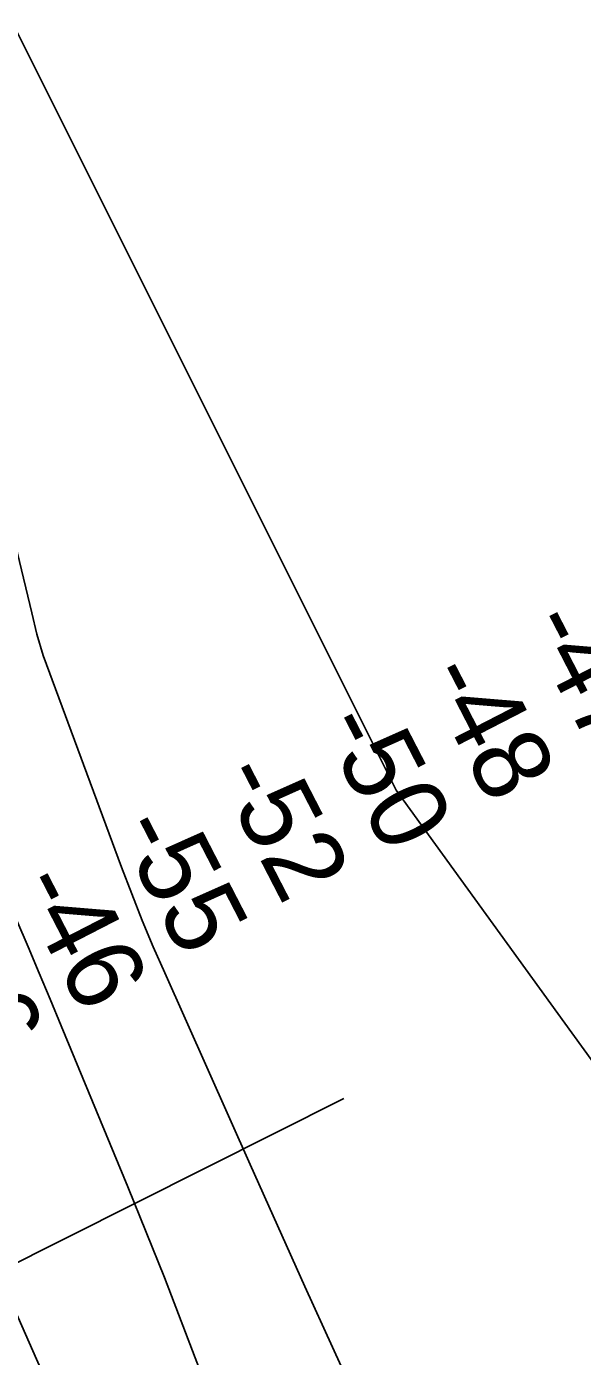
# Model space of a CAD drawing. Extents: x 3684037 to 3722149, y 433263 to 459021.
# Drawn here: x 3708721 to 3709206, y 440941 to 442103 of the extents above; entities that cross this region are included whole.
import ezdxf

# ---------------------------------------------------------------- set-up
doc = ezdxf.new("R2010")
doc.units = 0
for name, color, linetype in [('V-RIVR-EDGE', 7, 'Continuous'), ('V-RIVR-RANG', 7, 'Continuous'), ('V-TOPO-DPTH', 7, 'Continuous'), ('V-TOPO-MAJR', 7, 'Continuous'), ('V-TOPO-MINR', 7, 'Continuous')]:
    doc.layers.add(name, color=color, linetype=linetype)

msp = doc.modelspace()

# ---------------------------------------------------------------- linework, layer by layer
at = {"layer": 'V-RIVR-EDGE'}
msp.add_spline([(3705459.2609885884, 448025.4338505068), (3705478.181262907, 447991.0156329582), (3705490.6466582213, 447962.67892349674), (3705497.886274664, 447946.89059973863), (3705515.196078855, 447915.30695303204), (3705550.2240541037, 447853.7561290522), (3705577.199678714, 447806.37815928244), (3705592.0892782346, 447777.22671585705), (3705613.0133912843, 447735.5248869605), (3705627.0852571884, 447702.7361373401), (3705648.4127376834, 447660.6289412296), (3705670.9403216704, 447613.2619701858), (3705688.6394949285, 447575.6118136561), (3705703.1157281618, 447542.82206415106), (3705728.0505183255, 447487.76611454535), (3705750.155737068, 447433.12153145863), (3705764.2256032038, 447399.5240471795), (3705787.557922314, 447350.5376070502), (3705800.426685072, 447321.79553037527), (3705823.7710027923, 447277.66149819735), (3705853.129836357, 447212.8897339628), (3705867.200702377, 447179.69661701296), (3705884.5115064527, 447148.517337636), (3705906.216357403, 447095.49122375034), (3705936.00155575, 447039.61454087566), (3705952.47362864, 446996.3062413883), (3705954.4714680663, 446986.5964260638), (3705964.512659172, 446959.0744505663), (3705978.185157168, 446928.3085374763), (3706001.9328423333, 446883.76913808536), (3706017.2158104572, 446850.1686541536), (3706031.3046743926, 446824.25414913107), (3706060.2971362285, 446774.8493432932), (3706084.8695541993, 446736.77782140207), (3706095.754475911, 446723.40670266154), (3706096.150844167, 446720.17076414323), (3706091.2844378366, 446714.52162014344), (3706089.663968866, 446713.31251769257), (3706090.461704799, 446708.86247730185), (3706096.1148483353, 446705.61354028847), (3706102.9840935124, 446703.5747056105), (3706108.6282380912, 446696.68646263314), (3706116.2782211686, 446683.3233429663), (3706129.961717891, 446657.0054704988), (3706163.363224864, 446591.8193400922), (3706169.3887394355, 446575.6296486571), (3706187.0869128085, 446537.5751247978), (3706212.808440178, 446473.6210941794), (3706230.094247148, 446432.33263156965), (3706247.398052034, 446398.3227808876), (3706265.123222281, 446371.18617491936), (3706278.8077188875, 446345.27266978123), (3706293.681320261, 446309.65134908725), (3706314.591434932, 446262.28837758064), (3706333.5067098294, 446225.8483233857), (3706356.038293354, 446180.09882165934), (3706380.1853464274, 446133.5365857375), (3706396.283048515, 446102.36030601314), (3706412.7941168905, 446074.82233236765), (3706429.688555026, 446038.79164492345), (3706446.9753618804, 445997.9075496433), (3706455.379085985, 445962.3022270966), (3706478.2400455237, 445886.2241757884), (3706492.7132791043, 445852.221324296), (3706510.4004537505, 445809.7187598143), (3706528.098627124, 445771.6642359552), (3706558.2621958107, 445705.27300263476), (3706582.809616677, 445657.09229751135), (3706597.6902172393, 445624.3015481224), (3706628.25915314, 445558.3136822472), (3706659.6138263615, 445483.02336802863), (3706677.6863705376, 445432.8368244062), (3706696.968017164, 445381.0298118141), (3706750.0515385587, 445262.4181996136), (3706782.6343120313, 445193.1903956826), (3706806.7693664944, 445141.77575180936), (3706827.6774813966, 445093.60404564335), (3706850.971804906, 445029.251647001), (3706864.204939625, 444984.33387727), (3706871.8019288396, 444949.5392891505), (3706889.464106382, 444896.92754143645), (3706899.900665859, 444865.76526009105), (3706912.3530626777, 444832.1717753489), (3706928.848132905, 444798.1639244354), (3706942.5356291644, 444773.46352128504), (3706966.274315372, 444725.28481592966), (3706990.4233682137, 444679.53131466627), (3707016.9756276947, 444624.4713655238), (3707033.864066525, 444586.0144741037), (3707080.5137064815, 444481.9760839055), (3707095.3833083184, 444444.7372938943), (3707112.268747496, 444405.0673004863), (3707123.1276722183, 444381.1826311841), (3707171.385782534, 444273.5009354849), (3707203.15082239, 444200.6358253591), (3707218.0214241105, 444163.8014026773), (3707250.203829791, 444096.19206794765), (3707257.428447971, 444074.33823424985), (3707269.882844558, 444041.55348416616), (3707288.3577562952, 443990.55720600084), (3707304.028093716, 443950.0814775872), (3707342.974756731, 443837.9747386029), (3707365.860713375, 443772.0058705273), (3707378.693480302, 443728.70656999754), (3707379.8705864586, 443714.14634649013), (3707381.055691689, 443702.8210616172), (3707387.4745748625, 443682.1823296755), (3707398.330499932, 443657.0845583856), (3707418.0505099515, 443619.02503510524), (3707438.977622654, 443578.5363081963), (3707454.253591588, 443542.10525295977), (3707473.1368701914, 443492.7254442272), (3707483.176061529, 443464.3947340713), (3707531.0578012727, 443368.0363234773), (3707542.7274604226, 443344.9583890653), (3707550.7628130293, 443323.91129025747), (3707556.775329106, 443302.4648235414), (3707556.7633304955, 443297.61241559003), (3707558.764169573, 443289.1157022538), (3707568.429989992, 443273.3213791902), (3707583.724956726, 443244.5733032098), (3707593.778146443, 443221.9037356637), (3707598.205189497, 443213.40102302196), (3707609.506477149, 443204.8813123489), (3707611.9086839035, 443195.17049714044), (3707611.872688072, 443180.6132732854), (3707615.480997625, 443168.06888711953), (3707621.9068799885, 443150.26072648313), (3707634.3842739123, 443126.77642497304), (3707648.071770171, 443102.0760218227), (3707655.300387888, 443081.8396574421), (3707660.5361656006, 443073.3349450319), (3707674.23066105, 443051.46511318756), (3707678.635706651, 443034.0663193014), (3707682.6333852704, 443015.4554233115), (3707689.4656347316, 442998.4549974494), (3707701.917031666, 442964.4571453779), (3707713.9590618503, 442928.4384565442), (3707721.175680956, 442903.349684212), (3707726.3964604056, 442888.7794618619), (3707738.081117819, 442871.7670373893), (3707743.706264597, 442857.1958151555), (3707744.4850027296, 442845.0627955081), (3707747.2685794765, 442826.050531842), (3707753.7124597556, 442815.5209831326), (3707762.977912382, 442801.34512927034), (3707770.2135292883, 442783.9393361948), (3707772.585739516, 442762.0975011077), (3707776.166052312, 442738.23082972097), (3707779.760363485, 442720.02530094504), (3707786.591613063, 442702.6205077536), (3707805.499888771, 442663.34988225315), (3707822.7986942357, 442627.3181949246), (3707832.0301507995, 442599.39385186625), (3707839.2457700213, 442573.9007122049), (3707845.6846508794, 442561.3493268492), (3707852.5368980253, 442552.4362475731), (3707860.193880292, 442541.9036992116), (3707869.4663321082, 442530.55841665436), (3707886.3937664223, 442507.8718510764), (3707898.8601616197, 442479.9395089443), (3707916.135969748, 442434.60737304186), (3707928.5753680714, 442395.7571130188), (3707943.439970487, 442356.49648636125), (3707965.5811850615, 442316.40912712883), (3707989.726238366, 442269.0381565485), (3708009.8426166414, 442227.7426947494), (3708024.7172178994, 442192.5257413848), (3708061.3216672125, 442114.39185736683), (3708074.19742916, 442088.4803519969), (3708094.3098078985, 442045.5674208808), (3708116.024657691, 441996.5849802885), (3708126.0638490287, 441968.25427013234), (3708137.690513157, 441927.7885405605), (3708147.3253371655, 441899.4588302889), (3708157.761896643, 441868.2965489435), (3708179.0553810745, 441812.4408636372), (3708203.964174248, 441746.87136346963), (3708227.690861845, 441693.8402501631), (3708249.813078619, 441646.06991167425), (3708265.103045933, 441615.29999904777), (3708271.524928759, 441595.87436909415), (3708278.365177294, 441582.10888186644), (3708308.1063807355, 441508.4400365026), (3708330.6259656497, 441457.8381268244), (3708349.905612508, 441405.22237957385), (3708369.558630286, 441340.0702452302), (3708384.005866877, 441295.5538431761), (3708395.2611598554, 441268.4332353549), (3708411.757229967, 441234.82975177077), (3708423.4208898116, 441209.32561338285), (3708441.1150636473, 441169.65362020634), (3708458.4178686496, 441135.239402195), (3708469.274793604, 441110.54599823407), (3708475.28730968, 441089.09953151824), (3708486.945970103, 441061.5735564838), (3708507.055349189, 441017.44752338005), (3708523.5384208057, 440978.58726451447), (3708539.202758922, 440935.68533212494), (3708564.1435483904, 440883.0555864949), (3708587.089498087, 440841.3487581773), (3708595.1408488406, 440826.77153663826), (3708600.3546291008, 440809.3707429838), (3708606.7475152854, 440778.2184604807), (3708615.5866031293, 440755.14752525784), (3708636.8620896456, 440692.013228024), (3708652.91879648, 440644.25788779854), (3708673.412545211, 440592.04350822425), (3708688.685514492, 440554.3993509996), (3708705.9553233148, 440506.6410111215), (3708725.6613349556, 440462.92034523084), (3708743.353509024, 440422.43961739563), (3708759.4422121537, 440387.62403170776), (3708800.050339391, 440293.3054556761), (3708820.961453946, 440246.3468514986), (3708835.028320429, 440211.5362652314), (3708849.1041858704, 440180.3649849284), (3708876.059812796, 440124.89966857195), (3708892.157514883, 440093.72338884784), (3708912.2798924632, 440054.8541310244), (3708922.3300825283, 440030.97146149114), (3708931.9579073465, 439999.8111799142), (3708939.1845252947, 439978.7660808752), (3708948.0196136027, 439954.0776763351), (3708952.412660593, 439931.82647449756), (3708956.0019723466, 439911.59910907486), (3708960.015649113, 439899.45809035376), (3708969.6484733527, 439870.3196454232), (3708986.9362800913, 439829.8399174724), (3708999.3836774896, 439794.22459608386), (3709014.653647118, 439755.36733687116), (3709034.7480279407, 439705.1757938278), (3709046.79605743, 439671.58330896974), (3709063.280128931, 439633.1274174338), (3709075.7695214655, 439614.49552387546), (3709093.103322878, 439592.6166930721), (3709105.998082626, 439574.38816695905), (3709121.705415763, 439548.8740297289), (3709151.4686166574, 439484.1012656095), (3709171.5959936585, 439447.2538444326), (3709197.377514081, 439407.5618535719), (3709211.0500120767, 439376.7959404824), (3709222.3063049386, 439350.0796999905), (3709240.400846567, 439308.789237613), (3709252.8692415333, 439281.6656301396), (3709266.1473710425, 439254.94439022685), (3709270.9767816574, 439245.6319430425), (3709296.338936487, 439199.87544212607), (3709313.2213760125, 439158.99234673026), (3709331.3089184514, 439114.8713130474), (3709341.338110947, 439082.49692959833), (3709360.25438573, 439046.46124273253), (3709378.7622936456, 439008.80908643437), (3709407.717759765, 438944.44268941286), (3709416.407475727, 438923.6321006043)], degree=3, dxfattribs=at)
at = {"layer": 'V-RIVR-RANG'}
msp.add_line((3708319.1132000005, 440825.27049999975), (3708998.1321000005, 441166.64039999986), dxfattribs=at)
at = {"layer": 'V-TOPO-DPTH'}
for points in [[(3709009.52, 440303.11), (3708669.687304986, 441075.3251492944), (3708659.658509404, 441098.39599814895), (3708649.769239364, 441121.5257582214), (3708640.08925764, 441144.74388512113), (3708630.5488014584, 441168.020923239), (3708621.182264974, 441191.36938258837), (3708611.9080620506, 441214.7541449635), (3708602.772359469, 441238.19336187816), (3708593.7289904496, 441261.66888181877), (3708491.1548153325, 441530.3054668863), (3708456.1600394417, 441620.4667499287), (3708420.5087869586, 441710.3635082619), (3708383.872819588, 441799.8634795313), (3708346.5803756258, 441889.0989260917), (3708290.1373106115, 442022.10221289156), (3708280.546887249, 442044.62597398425), (3708270.920441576, 442067.13427770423), (3708261.2399624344, 442089.61939536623), (3708251.523460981, 442112.08905565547)], [(3708251.523460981, 442112.08905565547), (3708261.2399624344, 442089.61939536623), (3708270.920441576, 442067.13427770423), (3708280.546887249, 442044.62597398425), (3708290.1373106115, 442022.10221289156), (3708346.5803756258, 441889.0989260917), (3708383.872819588, 441799.8634795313), (3708420.5087869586, 441710.3635082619), (3708456.1600394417, 441620.4667499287), (3708491.1548153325, 441530.3054668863), (3708593.7289904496, 441261.66888181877), (3708602.772359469, 441238.19336187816), (3708611.9080620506, 441214.7541449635), (3708621.182264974, 441191.36938258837), (3708630.5488014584, 441168.020923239), (3708640.08925764, 441144.74388512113), (3708649.769239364, 441121.5257582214), (3708659.658509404, 441098.39599814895), (3708669.687304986, 441075.3251492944), (3709009.52, 440303.11)], [(3708872.2300191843, 440930.33706423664), (3708841.615073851, 441010.216581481), (3708809.771911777, 441089.64147170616), (3708751.4464032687, 441230.41736832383), (3708741.873967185, 441253.43330763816), (3708732.25996335, 441276.4318042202), (3708722.5836078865, 441299.40413670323), (3708712.8656846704, 441322.359026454), (3708601.3264724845, 441584.8356907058), (3708564.404036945, 441672.1000228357), (3708527.6632193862, 441759.44042188), (3708491.1948287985, 441846.89492129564), (3708454.9080561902, 441934.4254876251), (3708394.6830918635, 442080.341947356), (3708388.7726595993, 442095.01977278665), (3708383.0322990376, 442109.76213709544)], [(3708383.0322990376, 442109.76213709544), (3708388.7726595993, 442095.01977278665), (3708394.6830918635, 442080.341947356), (3708454.9080561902, 441934.4254876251), (3708491.1948287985, 441846.89492129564), (3708527.6632193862, 441759.44042188), (3708564.404036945, 441672.1000228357), (3708601.3264724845, 441584.8356907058), (3708712.8656846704, 441322.359026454), (3708722.5836078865, 441299.40413670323), (3708732.25996335, 441276.4318042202), (3708741.873967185, 441253.43330763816), (3708751.4464032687, 441230.41736832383), (3708809.771911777, 441089.64147170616), (3708841.615073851, 441010.216581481), (3708872.2300191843, 440930.33706423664)]]:
    msp.add_lwpolyline(points, dxfattribs=at)
at = {"layer": 'V-TOPO-MAJR'}
for points in [[(3708570.1306931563, 442239.12429414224), (3708725.796432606, 441591.05747622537), (3708730.155971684, 441572.41573712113), (3708735.854602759, 441554.0127207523), (3708804.183586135, 441369.0250672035), (3708813.071732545, 441345.6701763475), (3708822.2627514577, 441322.43856161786), (3708831.9080791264, 441299.3918610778), (3708841.856279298, 441276.4684366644), (3708916.4811807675, 441109.03264144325), (3708964.270274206, 441002.6214789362), (3709012.4607849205, 440896.39379594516), (3709061.253421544, 440790.4413322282), (3709110.447475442, 440684.672348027), (3709215.3058087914, 440460.88615475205), (3709225.2771220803, 440439.85713666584), (3709235.376338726, 440418.89045113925), (3709245.667410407, 440398.017264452), (3709256.0863854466, 440377.2064103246), (3710154.6707775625, 438932.2227807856)], [(3709411.773543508, 440927.5662885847), (3709338.2216111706, 441029.2685437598), (3709264.6698986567, 441130.9709579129), (3709191.1183326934, 441232.67347805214), (3709044, 441436.10000000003), (3708656.110118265, 442212.47821045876)]]:
    msp.add_lwpolyline(points, dxfattribs=at)
at = {"layer": 'V-TOPO-MINR'}
for points in [[(3708251.523460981, 442112.08905565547), (3708261.2399624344, 442089.61939536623), (3708270.920441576, 442067.13427770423), (3708280.546887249, 442044.62597398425), (3708290.1373106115, 442022.10221289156), (3708346.5803756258, 441889.0989260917), (3708383.872819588, 441799.8634795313), (3708420.5087869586, 441710.3635082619), (3708456.1600394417, 441620.4667499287), (3708491.1548153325, 441530.3054668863), (3708593.7289904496, 441261.66888181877), (3708602.772359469, 441238.19336187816), (3708611.9080620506, 441214.7541449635), (3708621.182264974, 441191.36938258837), (3708630.5488014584, 441168.020923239), (3708640.08925764, 441144.74388512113), (3708649.769239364, 441121.5257582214), (3708659.658509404, 441098.39599814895), (3708669.687304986, 441075.3251492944), (3709009.52, 440303.11)], [(3708383.0322990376, 442109.76213709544), (3708388.7726595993, 442095.01977278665), (3708394.6830918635, 442080.341947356), (3708454.9080561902, 441934.4254876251), (3708491.1948287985, 441846.89492129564), (3708527.6632193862, 441759.44042188), (3708564.404036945, 441672.1000228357), (3708601.3264724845, 441584.8356907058), (3708712.8656846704, 441322.359026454), (3708722.5836078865, 441299.40413670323), (3708732.25996335, 441276.4318042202), (3708741.873967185, 441253.43330763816), (3708751.4464032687, 441230.41736832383), (3708809.771911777, 441089.64147170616), (3708841.615073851, 441010.216581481), (3708872.2300191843, 440930.33706423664)]]:
    msp.add_lwpolyline(points, dxfattribs=at)

# ---------------------------------------------------------------- texts
at = {"layer": 'V-RIVR-RANG'}
for s, p in [('-47', (3709156.221737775, 441581.8085917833)), ('-48', (3709067.1023186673, 441536.4455707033)), ('-50', (3708977.0098542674, 441492.9688720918)), ('-52', (3708887.160048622, 441449.0232176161)), ('-55', (3708798.638366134, 441402.498305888)), ('-46', (3708711.3249774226, 441353.62861483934)), ('-36', (3708620.629366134, 441311.324305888))]:
    msp.add_text(s, height=66.99999999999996, rotation=297.2626111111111, dxfattribs=at).set_placement(p)

doc.saveas('drawing.dxf')
